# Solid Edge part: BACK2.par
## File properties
Author: Andrea Rangi V
Template: Ansi Metric part.par
Last saved by: Andrea Rangi V
Revision: 4
Application: Solid Edge
Accuracy: 0.990
Username: Andrea Rangi V
Face Style: Model Default
Coef. of Thermal Exp: 0.0
Thermal Conductivity: 0.0
Specific Heat: 0.0
Modulus of Elasticity: 0.0
Poisson's Ratio: 0.0
Yield Stress: 0.0
Ultimate Stress: 0.0
Elongation: 0.0
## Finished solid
Body 1: solid body, 77 faces, 222 edges, 144 vertices.
  Faces by surface: plane 74, swept 3
  Edges by curve: line 216, ellipse 6
Bounding box of the edges (mm; curved faces can reach further): 180.000 x 3.000 x 291.000, from (-68.2198, 0, -129.8168) to (111.7802, 3, 161.1832).
Planar faces by outward normal: +x 19, +y 1, +z 18, -x 17, -y 1, -z 18
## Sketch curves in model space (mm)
line (-65.2198, 0, -129.8168) -> (-38.2198, 0, -129.8168)
line (-68.2198, 0, 108.6832) -> (-68.2198, 0, 135.1832)
line (111.7802, 0, 108.6832) -> (111.7802, 0, 135.1832)
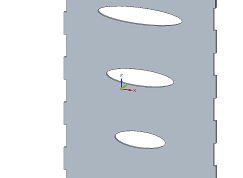
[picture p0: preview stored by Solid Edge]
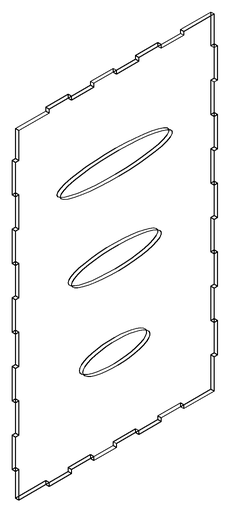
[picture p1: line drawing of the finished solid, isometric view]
